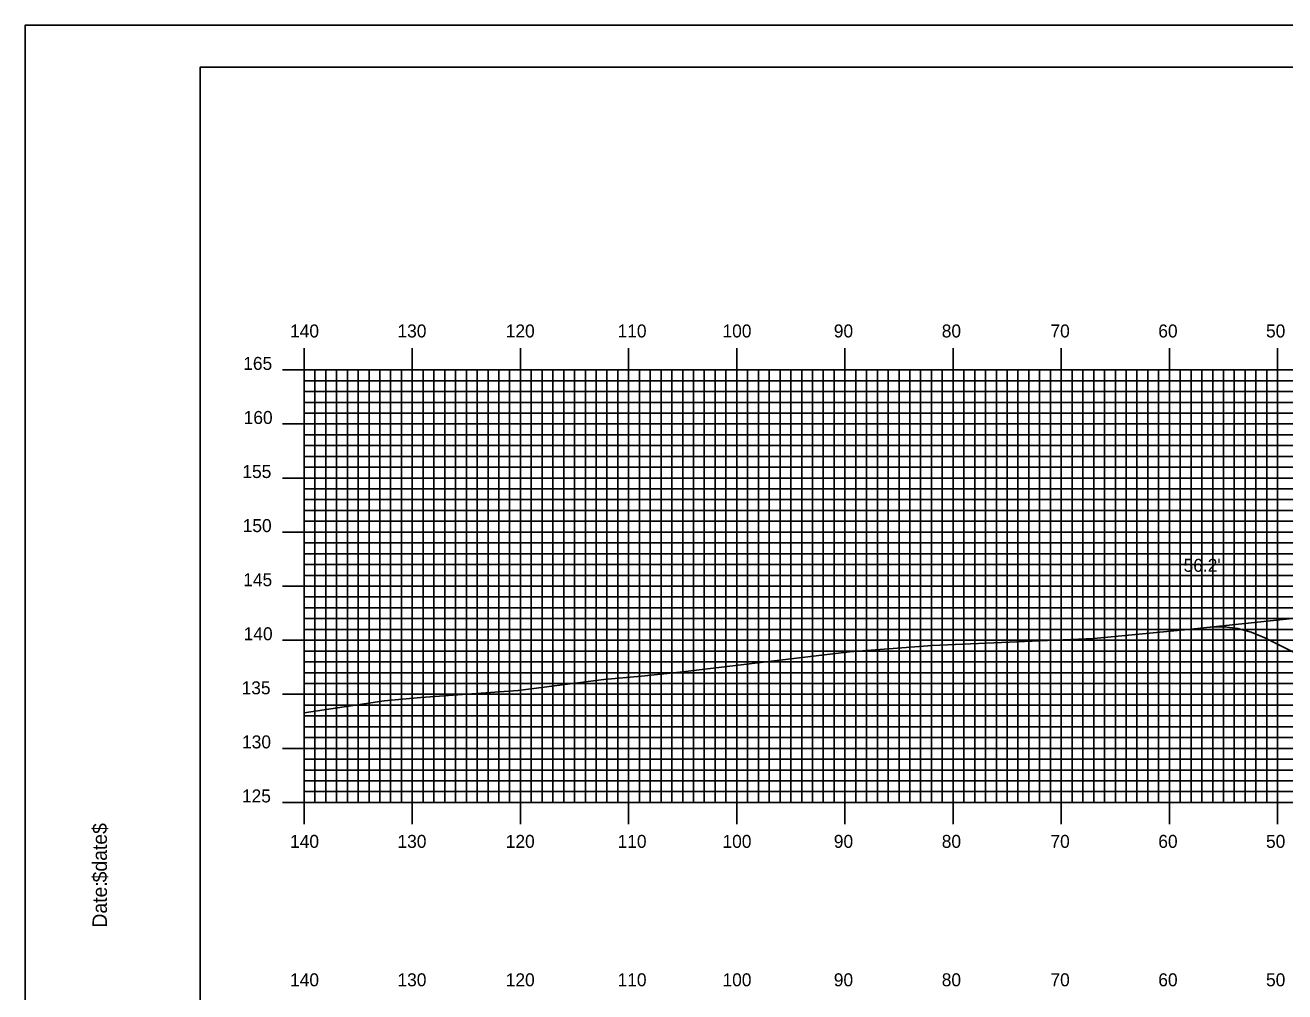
# Model space of a CAD drawing. Extents: x 1782647 to 1782990, y 442591 to 442811.
# Drawn here: x 1782647.2 to 1782763.6, y 442721.2 to 442810.5 of the extents above; entities that cross this region are included whole.
import ezdxf

# ---------------------------------------------------------------- set-up
doc = ezdxf.new("R2010")
doc.units = 0
for name, color, linetype in [('BORDER', 7, 'Continuous'), ('D_Roadway_Centerline', 7, 'Continuous'), ('D_Roadway_SlopeLines', 7, 'Continuous'), ('D_Text_Standard', 7, 'Continuous'), ('H_V ANNOTATION', 7, 'Continuous'), ('MAJOR', 7, 'Continuous'), ('MINOR', 7, 'Continuous'), ('PLOT BOUNDARY', 7, 'Continuous'), ('S_Roadway_Centerline', 7, 'Continuous')]:
    doc.layers.add(name, color=color, linetype=linetype)

msp = doc.modelspace()

# ---------------------------------------------------------------- linework, layer by layer
at = {"layer": 'BORDER'}
msp.add_lwpolyline([(1782663.35, 442596.67), (1782983.35, 442596.67), (1782983.35, 442806.67), (1782663.35, 442806.67)], close=True, dxfattribs=at)
at = {"layer": 'D_Roadway_Centerline'}
msp.add_lwpolyline([(1782756.76, 442754.88), (1782758.01, 442754.92), (1782759.26, 442754.76), (1782760.51, 442754.42), (1782761.76, 442753.89), (1782778.77, 442745.38), (1782782.77, 442746.38), (1782792.95, 442748.93), (1782800.95, 442749.25), (1782812.95, 442749.49), (1782824.95, 442749.25), (1782832.95, 442748.93), (1782843.12, 442746.38), (1782847.12, 442745.39), (1782886.31, 442764.98), (1782887.56, 442765.54), (1782888.81, 442765.97), (1782890.06, 442766.27), (1782891.31, 442766.44)], dxfattribs=at)
at = {"layer": 'D_Roadway_SlopeLines'}
msp.add_lwpolyline([(1782778.77, 442745.38), (1782761.76, 442753.89), (1782760.51, 442754.42), (1782759.26, 442754.76), (1782758.01, 442754.92), (1782756.76, 442754.88)], dxfattribs=at)
at = {"layer": 'MAJOR'}
for p, q in [((1782672.95, 442780.67), (1782672.95, 442778.67)), ((1782682.95, 442780.67), (1782682.95, 442778.67)), ((1782692.95, 442780.67), (1782692.95, 442778.67)), ((1782702.95, 442780.67), (1782702.95, 442778.67)), ((1782712.95, 442780.67), (1782712.95, 442778.67)), ((1782722.95, 442780.67), (1782722.95, 442778.67)), ((1782732.95, 442780.67), (1782732.95, 442778.67)), ((1782742.95, 442780.67), (1782742.95, 442778.67)), ((1782752.95, 442780.67), (1782752.95, 442778.67)), ((1782762.95, 442780.67), (1782762.95, 442778.67)), ((1782670.94, 442778.67), (1782672.95, 442778.67)), ((1782672.95, 442778.67), (1782952.95, 442778.67)), ((1782672.95, 442738.67), (1782672.95, 442778.67)), ((1782672.95, 442738.67), (1782672.95, 442778.67)), ((1782672.95, 442778.67), (1782952.95, 442778.67)), ((1782682.95, 442738.67), (1782682.95, 442778.67)), ((1782692.95, 442738.67), (1782692.95, 442778.67)), ((1782702.95, 442738.67), (1782702.95, 442778.67)), ((1782712.95, 442738.67), (1782712.95, 442778.67)), ((1782722.95, 442738.67), (1782722.95, 442778.67)), ((1782732.95, 442738.67), (1782732.95, 442778.67)), ((1782742.95, 442738.67), (1782742.95, 442778.67)), ((1782752.95, 442738.67), (1782752.95, 442778.67)), ((1782762.95, 442738.67), (1782762.95, 442778.67)), ((1782670.94, 442773.67), (1782672.95, 442773.67)), ((1782672.95, 442773.67), (1782952.95, 442773.67)), ((1782670.94, 442768.67), (1782672.95, 442768.67)), ((1782672.95, 442768.67), (1782952.95, 442768.67)), ((1782670.94, 442763.67), (1782672.95, 442763.67)), ((1782672.95, 442763.67), (1782952.95, 442763.67)), ((1782670.94, 442758.67), (1782672.95, 442758.67)), ((1782672.95, 442758.67), (1782952.95, 442758.67)), ((1782670.94, 442753.67), (1782672.95, 442753.67)), ((1782672.95, 442753.67), (1782952.95, 442753.67)), ((1782670.94, 442748.67), (1782672.95, 442748.67)), ((1782672.95, 442748.67), (1782952.95, 442748.67)), ((1782670.94, 442743.67), (1782672.95, 442743.67)), ((1782672.95, 442743.67), (1782952.95, 442743.67)), ((1782670.94, 442738.67), (1782672.95, 442738.67)), ((1782672.95, 442738.67), (1782952.95, 442738.67)), ((1782672.95, 442738.67), (1782952.95, 442738.67)), ((1782672.95, 442736.66), (1782672.95, 442738.67)), ((1782682.95, 442736.66), (1782682.95, 442738.67)), ((1782692.95, 442736.66), (1782692.95, 442738.67)), ((1782702.95, 442736.66), (1782702.95, 442738.67)), ((1782712.95, 442736.66), (1782712.95, 442738.67)), ((1782722.95, 442736.66), (1782722.95, 442738.67)), ((1782732.95, 442736.66), (1782732.95, 442738.67)), ((1782742.95, 442736.66), (1782742.95, 442738.67)), ((1782752.95, 442736.66), (1782752.95, 442738.67)), ((1782762.95, 442736.66), (1782762.95, 442738.67))]:
    msp.add_line(p, q, dxfattribs=at)
at = {"layer": 'MINOR'}
for p, q in [((1782672.95, 442777.67), (1782952.95, 442777.67)), ((1782672.95, 442777.67), (1782674.95, 442777.67)), ((1782673.95, 442738.67), (1782673.95, 442778.67)), ((1782674.95, 442738.67), (1782674.95, 442778.67)), ((1782675.95, 442738.67), (1782675.95, 442778.67)), ((1782676.95, 442738.67), (1782676.95, 442778.67)), ((1782677.95, 442738.67), (1782677.95, 442778.67)), ((1782678.95, 442738.67), (1782678.95, 442778.67)), ((1782679.95, 442738.67), (1782679.95, 442778.67)), ((1782680.95, 442738.67), (1782680.95, 442778.67)), ((1782681.95, 442738.67), (1782681.95, 442778.67)), ((1782683.95, 442738.67), (1782683.95, 442778.67)), ((1782684.95, 442738.67), (1782684.95, 442778.67)), ((1782685.95, 442738.67), (1782685.95, 442778.67)), ((1782686.95, 442738.67), (1782686.95, 442778.67)), ((1782687.95, 442738.67), (1782687.95, 442778.67)), ((1782688.95, 442738.67), (1782688.95, 442778.67)), ((1782689.95, 442738.67), (1782689.95, 442778.67)), ((1782690.95, 442738.67), (1782690.95, 442778.67)), ((1782691.95, 442738.67), (1782691.95, 442778.67)), ((1782693.95, 442738.67), (1782693.95, 442778.67)), ((1782694.95, 442738.67), (1782694.95, 442778.67)), ((1782695.95, 442738.67), (1782695.95, 442778.67)), ((1782696.95, 442738.67), (1782696.95, 442778.67)), ((1782697.95, 442738.67), (1782697.95, 442778.67)), ((1782698.95, 442738.67), (1782698.95, 442778.67)), ((1782699.95, 442738.67), (1782699.95, 442778.67)), ((1782700.95, 442738.67), (1782700.95, 442778.67)), ((1782701.95, 442738.67), (1782701.95, 442778.67)), ((1782703.95, 442738.67), (1782703.95, 442778.67)), ((1782704.95, 442738.67), (1782704.95, 442778.67)), ((1782705.95, 442738.67), (1782705.95, 442778.67)), ((1782706.95, 442738.67), (1782706.95, 442778.67)), ((1782707.95, 442738.67), (1782707.95, 442778.67)), ((1782708.95, 442738.67), (1782708.95, 442778.67)), ((1782709.95, 442738.67), (1782709.95, 442778.67)), ((1782710.95, 442738.67), (1782710.95, 442778.67)), ((1782711.95, 442738.67), (1782711.95, 442778.67)), ((1782713.95, 442738.67), (1782713.95, 442778.67)), ((1782714.95, 442738.67), (1782714.95, 442778.67)), ((1782715.95, 442738.67), (1782715.95, 442778.67)), ((1782716.95, 442738.67), (1782716.95, 442778.67)), ((1782717.95, 442738.67), (1782717.95, 442778.67)), ((1782718.95, 442738.67), (1782718.95, 442778.67)), ((1782719.95, 442738.67), (1782719.95, 442778.67)), ((1782720.95, 442738.67), (1782720.95, 442778.67)), ((1782721.95, 442738.67), (1782721.95, 442778.67)), ((1782723.95, 442738.67), (1782723.95, 442778.67)), ((1782724.95, 442738.67), (1782724.95, 442778.67)), ((1782725.95, 442738.67), (1782725.95, 442778.67)), ((1782726.95, 442738.67), (1782726.95, 442778.67)), ((1782727.95, 442738.67), (1782727.95, 442778.67)), ((1782728.95, 442738.67), (1782728.95, 442778.67)), ((1782729.95, 442738.67), (1782729.95, 442778.67)), ((1782730.95, 442738.67), (1782730.95, 442778.67)), ((1782731.95, 442738.67), (1782731.95, 442778.67)), ((1782733.95, 442738.67), (1782733.95, 442778.67)), ((1782734.95, 442738.67), (1782734.95, 442778.67)), ((1782735.95, 442738.67), (1782735.95, 442778.67)), ((1782736.95, 442738.67), (1782736.95, 442778.67)), ((1782737.95, 442738.67), (1782737.95, 442778.67)), ((1782738.95, 442738.67), (1782738.95, 442778.67)), ((1782739.95, 442738.67), (1782739.95, 442778.67)), ((1782740.95, 442738.67), (1782740.95, 442778.67)), ((1782741.95, 442738.67), (1782741.95, 442778.67)), ((1782743.95, 442738.67), (1782743.95, 442778.67)), ((1782744.95, 442738.67), (1782744.95, 442778.67)), ((1782745.95, 442738.67), (1782745.95, 442778.67)), ((1782746.95, 442738.67), (1782746.95, 442778.67)), ((1782747.95, 442738.67), (1782747.95, 442778.67)), ((1782748.95, 442738.67), (1782748.95, 442778.67)), ((1782749.95, 442738.67), (1782749.95, 442778.67)), ((1782750.95, 442738.67), (1782750.95, 442778.67)), ((1782751.95, 442738.67), (1782751.95, 442778.67)), ((1782753.95, 442738.67), (1782753.95, 442778.67)), ((1782754.95, 442738.67), (1782754.95, 442778.67)), ((1782755.95, 442738.67), (1782755.95, 442778.67)), ((1782756.95, 442738.67), (1782756.95, 442778.67)), ((1782757.95, 442738.67), (1782757.95, 442778.67)), ((1782758.95, 442738.67), (1782758.95, 442778.67)), ((1782759.95, 442738.67), (1782759.95, 442778.67)), ((1782760.95, 442738.67), (1782760.95, 442778.67)), ((1782761.95, 442738.67), (1782761.95, 442778.67)), ((1782672.95, 442776.67), (1782952.95, 442776.67)), ((1782672.95, 442776.67), (1782674.95, 442776.67)), ((1782672.95, 442775.67), (1782952.95, 442775.67)), ((1782672.95, 442775.67), (1782674.95, 442775.67)), ((1782672.95, 442774.67), (1782952.95, 442774.67)), ((1782672.95, 442774.67), (1782674.95, 442774.67)), ((1782672.95, 442772.67), (1782952.95, 442772.67)), ((1782672.95, 442772.67), (1782674.95, 442772.67)), ((1782672.95, 442771.67), (1782952.95, 442771.67)), ((1782672.95, 442771.67), (1782674.95, 442771.67)), ((1782672.95, 442770.67), (1782952.95, 442770.67)), ((1782672.95, 442770.67), (1782674.95, 442770.67)), ((1782672.95, 442769.67), (1782952.95, 442769.67)), ((1782672.95, 442769.67), (1782674.95, 442769.67)), ((1782672.95, 442767.67), (1782952.95, 442767.67)), ((1782672.95, 442767.67), (1782674.95, 442767.67)), ((1782672.95, 442766.67), (1782952.95, 442766.67)), ((1782672.95, 442766.67), (1782674.95, 442766.67)), ((1782672.95, 442765.67), (1782952.95, 442765.67)), ((1782672.95, 442765.67), (1782674.95, 442765.67)), ((1782672.95, 442764.67), (1782952.95, 442764.67)), ((1782672.95, 442764.67), (1782674.95, 442764.67)), ((1782672.95, 442762.67), (1782952.95, 442762.67)), ((1782672.95, 442762.67), (1782674.95, 442762.67)), ((1782672.95, 442761.67), (1782952.95, 442761.67)), ((1782672.95, 442761.67), (1782674.95, 442761.67)), ((1782672.95, 442760.67), (1782952.95, 442760.67)), ((1782672.95, 442760.67), (1782674.95, 442760.67)), ((1782672.95, 442759.67), (1782952.95, 442759.67)), ((1782672.95, 442759.67), (1782674.95, 442759.67)), ((1782672.95, 442757.67), (1782952.95, 442757.67)), ((1782672.95, 442757.67), (1782674.95, 442757.67)), ((1782672.95, 442756.67), (1782952.95, 442756.67)), ((1782672.95, 442756.67), (1782674.95, 442756.67)), ((1782672.95, 442755.67), (1782952.95, 442755.67)), ((1782672.95, 442755.67), (1782674.95, 442755.67)), ((1782672.95, 442754.67), (1782952.95, 442754.67)), ((1782672.95, 442754.67), (1782674.95, 442754.67)), ((1782672.95, 442752.67), (1782952.95, 442752.67)), ((1782672.95, 442752.67), (1782674.95, 442752.67)), ((1782672.95, 442751.67), (1782952.95, 442751.67)), ((1782672.95, 442751.67), (1782674.95, 442751.67)), ((1782672.95, 442750.67), (1782952.95, 442750.67)), ((1782672.95, 442750.67), (1782674.95, 442750.67)), ((1782672.95, 442749.67), (1782952.95, 442749.67)), ((1782672.95, 442749.67), (1782674.95, 442749.67)), ((1782672.95, 442747.67), (1782952.95, 442747.67)), ((1782672.95, 442747.67), (1782674.95, 442747.67)), ((1782672.95, 442746.67), (1782952.95, 442746.67)), ((1782672.95, 442746.67), (1782674.95, 442746.67)), ((1782672.95, 442745.67), (1782952.95, 442745.67)), ((1782672.95, 442745.67), (1782674.95, 442745.67)), ((1782672.95, 442744.67), (1782952.95, 442744.67)), ((1782672.95, 442744.67), (1782674.95, 442744.67)), ((1782672.95, 442742.67), (1782952.95, 442742.67)), ((1782672.95, 442742.67), (1782674.95, 442742.67)), ((1782672.95, 442741.67), (1782952.95, 442741.67)), ((1782672.95, 442741.67), (1782674.95, 442741.67)), ((1782672.95, 442740.67), (1782952.95, 442740.67)), ((1782672.95, 442740.67), (1782674.95, 442740.67)), ((1782672.95, 442739.67), (1782952.95, 442739.67)), ((1782672.95, 442739.67), (1782674.95, 442739.67))]:
    msp.add_line(p, q, dxfattribs=at)
at = {"layer": 'PLOT BOUNDARY'}
msp.add_lwpolyline([(1782647.16, 442590.55), (1782987.16, 442590.55), (1782987.16, 442810.55), (1782647.16, 442810.55)], close=True, dxfattribs=at)
at = {"layer": 'S_Roadway_Centerline'}
msp.add_lwpolyline([(1782672.95, 442746.96), (1782680.36, 442748.07), (1782683.73, 442748.39), (1782692.74, 442749.01), (1782700.67, 442750.03), (1782704.13, 442750.35), (1782707.7, 442750.73), (1782723.38, 442752.6), (1782731.01, 442753.19), (1782745.96, 442753.83), (1782754.65, 442754.66), (1782769.59, 442756.23)], dxfattribs=at)

# ---------------------------------------------------------------- texts
at = {"layer": 'BORDER'}
for s, p in [('$date$', (1782654.72, 442731.28)), ('$date$', (1782654.72, 442731.28)), ('Date:', (1782654.72, 442727.1)), ('Date:', (1782654.72, 442727.1))]:
    msp.add_text(s, height=1.339, rotation=90, dxfattribs=at).set_placement(p)
at = {"layer": 'D_Text_Standard'}
msp.add_text("56.2'", height=1.2, dxfattribs=at).set_placement((1782754.26, 442760))
at = {"layer": 'H_V ANNOTATION'}
for s, p in [('140', (1782671.65, 442781.67)), ('130', (1782681.58, 442781.67)), ('120', (1782691.59, 442781.67)), ('110', (1782701.93, 442781.67)), ('100', (1782711.63, 442781.67)), ('90', (1782721.92, 442781.67)), ('80', (1782731.9, 442781.67)), ('70', (1782741.95, 442781.67)), ('60', (1782751.92, 442781.67)), ('50', (1782761.88, 442781.67)), ('165', (1782667.32, 442778.67)), ('160', (1782667.36, 442773.67)), ('155', (1782667.24, 442768.67)), ('150', (1782667.27, 442763.67)), ('145', (1782667.32, 442758.67)), ('140', (1782667.36, 442753.67)), ('135', (1782667.17, 442748.67)), ('130', (1782667.21, 442743.67)), ('125', (1782667.2, 442738.67)), ('140', (1782671.65, 442734.47)), ('130', (1782681.58, 442734.47)), ('120', (1782691.59, 442734.47)), ('110', (1782701.93, 442734.47)), ('100', (1782711.63, 442734.47)), ('90', (1782721.92, 442734.47)), ('80', (1782731.9, 442734.47)), ('70', (1782741.95, 442734.47)), ('60', (1782751.92, 442734.47)), ('50', (1782761.88, 442734.47)), ('140', (1782671.65, 442721.67)), ('130', (1782681.58, 442721.67)), ('120', (1782691.59, 442721.67)), ('110', (1782701.93, 442721.67)), ('100', (1782711.63, 442721.67)), ('90', (1782721.92, 442721.67)), ('80', (1782731.9, 442721.67)), ('70', (1782741.95, 442721.67)), ('60', (1782751.92, 442721.67)), ('50', (1782761.88, 442721.67))]:
    msp.add_text(s, height=1.2, dxfattribs=at).set_placement(p)
at = {"layer": 'MAJOR'}
msp.add_text('-', height=0.012, dxfattribs=at).set_placement((1782672.94, 442738.67))

doc.saveas('drawing.dxf')
